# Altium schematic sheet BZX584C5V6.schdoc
size 127 x 101 mm
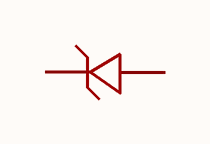
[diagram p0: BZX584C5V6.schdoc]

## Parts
ZD?  bzx584c5v6_c48667  [SOD-523F_L1.2-W0.8-LS1.7-RD]  (value not drawn)

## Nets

Not connected (* = marked no-connect by the designer): ZD? 1(K) 2(A)

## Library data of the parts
ZD? = bzx584c5v6_c48667: 二极管配置:1个独立式;稳压值(标称值):5.6V;稳压值(范围值):5.2V~6V;耗散功率(Pd):150mW;; Manufacturer: CJ(江苏长电/长晶); AddInBom: yes; ModelId: 1a3524270898456e95fda80dc56db1b2; ModelName: SOD-523F_L1.2-W0.8-H0.6-LS1.6; ModelTransform: 62.992,31.496,0,0,0,0,-0.005,0.16,0; Diode Configuration: 1个独立式; Zener Voltage(Nom): 5.6V; Reverse Leakage Current (Ir): 1uA@2V; Pd - Power Dissipation: 150mW; Impedance(Zzt): 40Ω; Impedance(Zzk): 400Ω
